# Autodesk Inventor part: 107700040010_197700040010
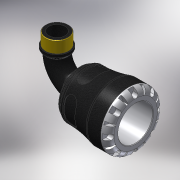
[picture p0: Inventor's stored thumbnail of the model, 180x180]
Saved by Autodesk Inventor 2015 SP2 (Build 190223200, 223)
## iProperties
Created: 2016-12
Part Number: 107700040010_197700040010
Material: PVC-Piping
Description: PLASSON 90° ELBOW WITH MALE INTEGRAL BRASS 40X1" SERIES 1
Document SubType Name: Modeling
Designer: KIM
Mass: 664.223 g
Surface Area: 733.008 cm^2
Volume: 474.445 cm^3
Density: 1.4 g/cm^3
Appearance: Black Cast
Author: KIM
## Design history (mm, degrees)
derived "1077.ipt"
feature "Solid1::1077.ipt"
tag "TaggingFeature1"
body "Solid1"
other parameters: "d1" = 29.82, "d8" = 59.5, "d13" = 8, "d14" = 8, "d15" = 0, "d17" = 360 deg, "d19" = 8 deg, "d20" = 0.8, "d21" = 0.8, "d22" = 8 deg, "d24" = 0, "d26" = 360 deg, "d33" = 7, "d43" = 54.6, "d51" = 0.7, "d54" = 14, "d55" = 8.8, "d57" = 15.68, "d58" = 0, "d74" = 0, "d78" = 71, "d82" = 0.8, "d115" = 360 deg, "d207" = 90 deg, "d228" = 11.9, "d247" = 1.4, "d248" = 4.26, "d268" = 32.725, "d269" = 4.26, "d270" = 104, "d276" = 33.249, "d277" = 19, "d278" = 36.5739, "d279" = 59, "d280" = 24.7, "d281" = 4.98735, "d283" = 29.9241, "d286" = 0, "d287" = 0, "d288" = 23.2743, "d290" = 12.33795, "d292" = 30 deg, "d294" = 3.3249, "d296" = 30 deg, "l_" = 71, "A_" = 104, "A_1" = 59, "l_2" = 19, "R_" = 33.249, "d289" = 23.2743
